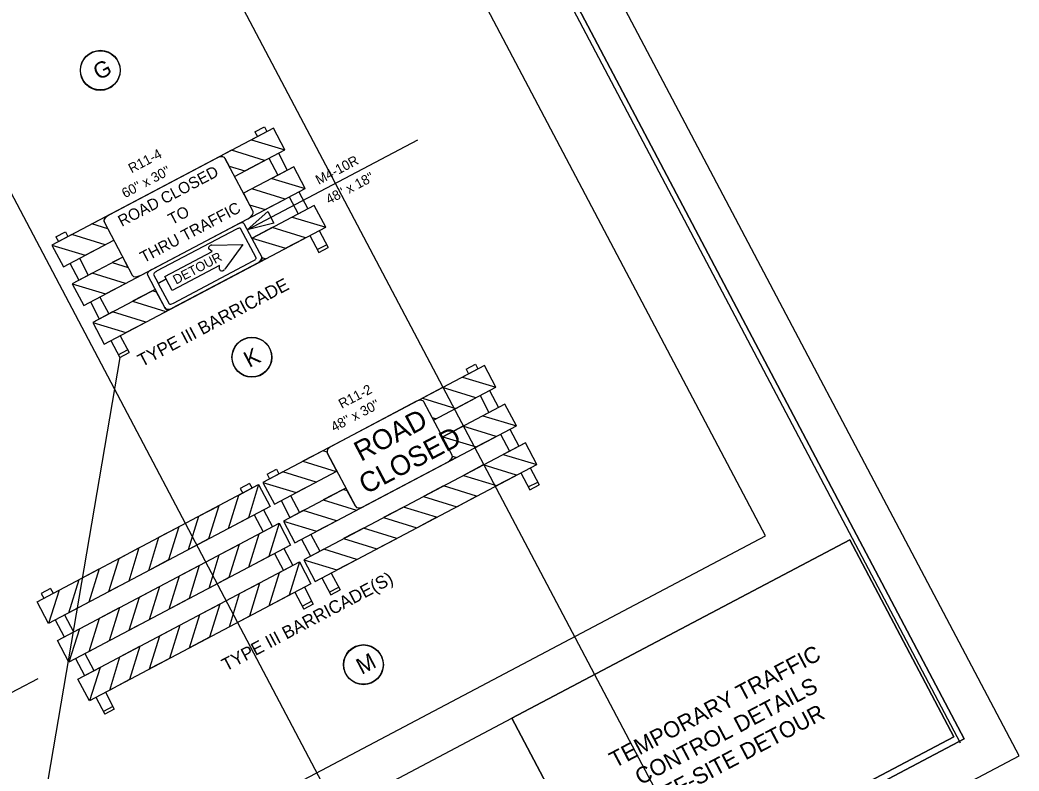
# Model space of a CAD drawing. Extents: x 1487176 to 2935813, y 497724 to 1002340.
# Drawn here: x 1489024 to 1489641, y 498716 to 499179 of the extents above; entities that cross this region are included whole.
import ezdxf

# ---------------------------------------------------------------- set-up
doc = ezdxf.new("R2010")
doc.units = 0
for name, color, linetype in [('DEV BORDER CELL', 7, 'Continuous'), ('DEV TYPE 3 BARRICADE DOUBLE WITH R11-2 CELL', 7, 'Continuous'), ('DEV TYPE 3 BARRICADE WITH R11-4 M4-10L CELL', 7, 'Continuous'), ('Gray Area Fill Shapes', 7, 'Continuous'), ('Scratch_Level_0', 7, 'Continuous'), ('Scratch_Level_1', 7, 'Continuous'), ('Scratch_Level_3', 7, 'Continuous'), ('Scratch_Level_5', 7, 'Continuous'), ('Sheet Plot Border Outside CELL', 7, 'Continuous'), ('WZ OSDHWYEND CELL', 7, 'Continuous'), ('WZ OSDHWYS CELL', 7, 'Continuous'), ('WZ OSDR CELL', 7, 'Continuous')]:
    doc.layers.add(name, color=color, linetype=linetype)

msp = doc.modelspace()

# ---------------------------------------------------------------- linework, layer by layer
at = {"layer": 'DEV BORDER CELL'}
for points in [[(1489116.94, 499663.96), (1487790.49, 498963.57), (1488280.77, 498035.05), (1489607.21, 498735.45)], [(1489536.46, 498858.41), (1489327.77, 498748.22), (1489391.98, 498626.62), (1489600.67, 498736.82)], [(1489226.96, 498694.98), (1489327.77, 498748.22), (1489391.98, 498626.62), (1489291.16, 498573.39)]]:
    msp.add_lwpolyline(points, close=True, dxfattribs=at)
at = {"layer": 'DEV TYPE 3 BARRICADE DOUBLE WITH R11-2 CELL'}
for p, q in [((1489310.86, 498966.09), (1489174.03, 498893.84)), ((1489310.86, 498966.09), (1489297.21, 498958.89)), ((1489299.46, 498963.78), (1489305.26, 498966.85)), ((1489305.26, 498966.85), (1489306.8, 498963.95)), ((1489317.95, 498952.68), (1489310.86, 498966.09)), ((1489317.95, 498952.68), (1489310.86, 498966.09)), ((1489299.46, 498963.78), (1489300.99, 498960.88)), ((1489297.21, 498958.89), (1489317.95, 498952.68)), ((1489284.9, 498952.38), (1489272.59, 498945.88)), ((1489279.36, 498932.3), (1489317.95, 498952.68)), ((1489305.4, 498946.05), (1489284.9, 498952.38)), ((1489308.07, 498947.46), (1489313.59, 498937.01)), ((1489313.88, 498950.53), (1489319.4, 498940.07)), ((1489272.59, 498945.88), (1489293.09, 498939.55)), ((1489323.47, 498942.22), (1489284.88, 498921.85)), ((1489293.09, 498939.55), (1489305.4, 498946.05)), ((1489323.47, 498942.22), (1489309.82, 498935.01)), ((1489330.55, 498928.8), (1489323.47, 498942.22)), ((1489330.55, 498928.8), (1489323.47, 498942.22)), ((1489309.82, 498935.01), (1489330.55, 498928.8)), ((1489193.71, 498856.55), (1489330.55, 498928.8)), ((1489280.78, 498933.05), (1489278.61, 498933.72)), ((1489278.61, 498933.72), (1489279.36, 498932.3)), ((1489279.36, 498932.3), (1489280.78, 498933.05)), ((1489297.51, 498928.51), (1489285.19, 498922.01)), ((1489318.01, 498922.18), (1489297.51, 498928.51)), ((1489320.68, 498923.59), (1489326.2, 498913.14)), ((1489326.49, 498926.66), (1489332.01, 498916.2)), ((1489336.07, 498918.35), (1489199.23, 498846.1)), ((1489285.19, 498922.01), (1489305.69, 498915.68)), ((1489305.69, 498915.68), (1489318.01, 498922.18)), ((1489336.07, 498918.35), (1489322.42, 498911.14)), ((1489343.16, 498904.93), (1489336.07, 498918.35)), ((1489343.16, 498904.93), (1489336.07, 498918.35)), ((1489210.96, 498913.34), (1489198.65, 498906.84)), ((1489213.6, 498912.53), (1489210.96, 498913.34)), ((1489219.7, 498900.8), (1489213.76, 498912.04)), ((1489322.42, 498911.14), (1489343.16, 498904.93)), ((1489198.65, 498906.84), (1489219.15, 498900.51)), ((1489206.32, 498832.68), (1489343.16, 498904.93)), ((1489235.78, 498878.77), (1489288.48, 498906.59)), ((1489288.48, 498906.59), (1489293.38, 498909.18)), ((1489293.38, 498909.18), (1489291, 498909.91)), ((1489310.11, 498904.64), (1489297.8, 498898.14)), ((1489330.61, 498898.31), (1489310.11, 498904.64)), ((1489186.34, 498900.34), (1489174.03, 498893.84)), ((1489176.56, 498898.89), (1489182.37, 498901.96)), ((1489176.56, 498898.89), (1489178.09, 498895.99)), ((1489181.11, 498880.42), (1489219.7, 498900.8)), ((1489182.37, 498901.96), (1489183.9, 498899.05)), ((1489206.84, 498894.01), (1489186.34, 498900.34)), ((1489219.15, 498900.51), (1489219.7, 498900.8)), ((1489297.8, 498898.14), (1489318.3, 498891.81)), ((1489318.3, 498891.81), (1489330.61, 498898.31)), ((1489333.28, 498899.72), (1489338.8, 498889.27)), ((1489339.09, 498902.79), (1489344.61, 498892.33)), ((1489034.52, 498820.17), (1489171.35, 498892.43)), ((1489159.04, 498885.93), (1489171.35, 498892.43)), ((1489165.75, 498893.19), (1489159.95, 498890.12)), ((1489171.35, 498892.43), (1489165.02, 498871.93)), ((1489165.75, 498893.19), (1489167.29, 498890.28)), ((1489171.35, 498892.43), (1489178.44, 498879.01)), ((1489174.03, 498893.84), (1489181.11, 498880.42)), ((1489174.03, 498893.84), (1489194.53, 498887.51)), ((1489194.53, 498887.51), (1489206.84, 498894.01)), ((1489285.48, 498891.64), (1489273.17, 498885.14)), ((1489305.98, 498885.31), (1489285.48, 498891.64)), ((1489337.88, 498891.01), (1489343.69, 498894.07)), ((1489338.8, 498889.27), (1489344.61, 498892.33)), ((1489152.71, 498865.43), (1489159.04, 498885.93)), ((1489159.95, 498890.12), (1489161.48, 498887.21)), ((1489225.22, 498890.34), (1489186.63, 498869.97)), ((1489190.98, 498885.64), (1489196.5, 498875.18)), ((1489223.57, 498889.47), (1489211.26, 498882.97)), ((1489226.09, 498888.69), (1489223.57, 498889.47)), ((1489231.15, 498879.1), (1489226.09, 498888.69)), ((1489293.67, 498878.8), (1489305.98, 498885.31)), ((1489134.41, 498872.92), (1489146.73, 498879.42)), ((1489146.73, 498879.42), (1489140.39, 498858.92)), ((1489185.18, 498882.57), (1489190.7, 498872.11)), ((1489211.26, 498882.97), (1489231.76, 498876.64)), ((1489273.17, 498885.14), (1489293.67, 498878.8)), ((1489178.44, 498879.01), (1489041.6, 498806.76)), ((1489128.08, 498852.42), (1489134.41, 498872.92)), ((1489168.56, 498873.8), (1489174.08, 498863.34)), ((1489174.37, 498876.86), (1489179.89, 498866.41)), ((1489198.94, 498876.47), (1489186.63, 498869.97)), ((1489219.44, 498870.14), (1489198.94, 498876.47)), ((1489231.76, 498876.64), (1489235.76, 498878.75)), ((1489260.8, 498878.6), (1489248.49, 498872.1)), ((1489281.3, 498872.27), (1489260.8, 498878.6)), ((1489047.12, 498796.3), (1489183.96, 498868.56)), ((1489165.02, 498871.93), (1489152.71, 498865.43)), ((1489171.64, 498862.06), (1489183.96, 498868.56)), ((1489183.96, 498868.56), (1489177.63, 498848.06)), ((1489183.96, 498868.56), (1489191.04, 498855.14)), ((1489186.63, 498869.97), (1489193.71, 498856.55)), ((1489186.63, 498869.97), (1489207.13, 498863.64)), ((1489207.13, 498863.64), (1489219.44, 498870.14)), ((1489248.49, 498872.1), (1489268.99, 498865.77)), ((1489268.99, 498865.77), (1489281.3, 498872.27)), ((1489109.79, 498859.92), (1489122.1, 498866.42)), ((1489122.1, 498866.42), (1489115.77, 498845.92)), ((1489165.31, 498841.55), (1489171.64, 498862.06)), ((1489203.59, 498861.76), (1489209.11, 498851.31)), ((1489236.17, 498865.6), (1489223.86, 498859.1)), ((1489256.67, 498859.27), (1489236.17, 498865.6)), ((1489191.04, 498855.14), (1489054.2, 498782.89)), ((1489103.46, 498839.42), (1489109.79, 498859.92)), ((1489140.39, 498858.92), (1489128.08, 498852.42)), ((1489147.02, 498849.05), (1489159.33, 498855.55)), ((1489159.33, 498855.55), (1489153, 498835.05)), ((1489197.78, 498858.7), (1489203.3, 498848.24)), ((1489223.86, 498859.1), (1489244.36, 498852.77)), ((1489244.36, 498852.77), (1489256.67, 498859.27)), ((1489085.1, 498846.89), (1489097.42, 498853.39)), ((1489097.42, 498853.39), (1489091.08, 498832.89)), ((1489140.69, 498828.55), (1489147.02, 498849.05)), ((1489181.17, 498849.93), (1489186.69, 498839.47)), ((1489186.98, 498852.99), (1489192.5, 498842.54)), ((1489211.55, 498852.6), (1489199.23, 498846.1)), ((1489232.05, 498846.27), (1489211.55, 498852.6)), ((1489059.72, 498772.43), (1489196.56, 498844.69)), ((1489078.77, 498826.39), (1489085.1, 498846.89)), ((1489115.77, 498845.92), (1489103.46, 498839.42)), ((1489122.39, 498836.05), (1489134.71, 498842.55)), ((1489134.71, 498842.55), (1489128.37, 498822.05)), ((1489177.63, 498848.06), (1489165.31, 498841.55)), ((1489184.25, 498838.18), (1489196.56, 498844.69)), ((1489196.56, 498844.69), (1489190.23, 498824.18)), ((1489196.56, 498844.69), (1489203.65, 498831.27)), ((1489199.23, 498846.1), (1489219.74, 498839.76)), ((1489199.23, 498846.1), (1489206.32, 498832.68)), ((1489219.74, 498839.76), (1489232.05, 498846.27)), ((1489060.48, 498833.88), (1489072.79, 498840.38)), ((1489072.79, 498840.38), (1489066.46, 498819.88)), ((1489116.06, 498815.55), (1489122.39, 498836.05)), ((1489177.92, 498817.68), (1489184.25, 498838.18)), ((1489216.19, 498837.89), (1489221.71, 498827.44)), ((1489054.15, 498813.38), (1489060.48, 498833.88)), ((1489203.65, 498831.27), (1489066.81, 498759.02)), ((1489091.08, 498832.89), (1489078.77, 498826.39)), ((1489153, 498835.05), (1489140.69, 498828.55)), ((1489159.62, 498825.18), (1489171.94, 498831.68)), ((1489171.94, 498831.68), (1489165.6, 498811.18)), ((1489210.38, 498834.83), (1489215.9, 498824.37)), ((1489034.52, 498820.17), (1489048.16, 498827.38)), ((1489042.86, 498828.29), (1489037.05, 498825.23)), ((1489037.05, 498825.23), (1489038.58, 498822.32)), ((1489048.16, 498827.38), (1489041.6, 498806.76)), ((1489042.86, 498828.29), (1489044.39, 498825.39)), ((1489097.71, 498823.02), (1489110.02, 498829.52)), ((1489110.02, 498829.52), (1489103.69, 498809.02)), ((1489153.29, 498804.68), (1489159.62, 498825.18)), ((1489190.23, 498824.18), (1489177.92, 498817.68)), ((1489193.77, 498826.06), (1489199.29, 498815.6)), ((1489199.58, 498829.12), (1489205.1, 498818.67)), ((1489214.98, 498826.11), (1489220.79, 498829.18)), ((1489215.9, 498824.37), (1489221.71, 498827.44)), ((1489041.6, 498806.76), (1489034.52, 498820.17)), ((1489041.6, 498806.76), (1489034.52, 498820.17)), ((1489066.46, 498819.88), (1489054.15, 498813.38)), ((1489091.38, 498802.51), (1489097.71, 498823.02)), ((1489128.37, 498822.05), (1489116.06, 498815.55)), ((1489135, 498812.18), (1489147.31, 498818.68)), ((1489147.31, 498818.68), (1489140.98, 498798.18)), ((1489204.18, 498820.41), (1489198.37, 498817.34)), ((1489205.1, 498818.67), (1489199.29, 498815.6)), ((1489051.47, 498811.97), (1489056.99, 498801.52)), ((1489073.08, 498810.01), (1489085.4, 498816.51)), ((1489085.4, 498816.51), (1489079.06, 498796.01)), ((1489128.66, 498791.68), (1489135, 498812.18)), ((1489045.67, 498808.9), (1489051.19, 498798.45)), ((1489066.75, 498789.51), (1489073.08, 498810.01)), ((1489103.69, 498809.02), (1489091.38, 498802.51)), ((1489110.31, 498799.14), (1489122.63, 498805.65)), ((1489122.63, 498805.65), (1489116.29, 498785.14)), ((1489165.6, 498811.18), (1489153.29, 498804.68)), ((1489047.12, 498796.3), (1489060.77, 498803.51)), ((1489060.77, 498803.51), (1489054.2, 498782.89)), ((1489103.98, 498778.64), (1489110.31, 498799.14)), ((1489054.2, 498782.89), (1489047.12, 498796.3)), ((1489054.2, 498782.89), (1489047.12, 498796.3)), ((1489079.06, 498796.01), (1489066.75, 498789.51)), ((1489140.98, 498798.18), (1489128.66, 498791.68)), ((1489064.08, 498788.1), (1489069.6, 498777.65)), ((1489085.69, 498786.14), (1489098, 498792.64)), ((1489098, 498792.64), (1489091.67, 498772.14)), ((1489058.27, 498785.03), (1489063.79, 498774.58)), ((1489079.35, 498765.64), (1489085.69, 498786.14)), ((1489116.29, 498785.14), (1489103.98, 498778.64)), ((1489059.72, 498772.43), (1489073.37, 498779.64)), ((1489073.37, 498779.64), (1489066.81, 498759.02)), ((1489066.81, 498759.02), (1489059.72, 498772.43)), ((1489066.81, 498759.02), (1489059.72, 498772.43)), ((1489091.67, 498772.14), (1489079.35, 498765.64)), ((1489076.68, 498764.23), (1489082.2, 498753.77)), ((1489070.87, 498761.16), (1489076.39, 498750.71)), ((1489081.28, 498755.52), (1489075.47, 498752.45)), ((1489082.2, 498753.77), (1489076.39, 498750.71))]:
    msp.add_line(p, q, dxfattribs=at)
for points in [[(1489268.79, 498943.88), (1489216.09, 498916.05)], [(1489290.82, 498910.6), (1489273.42, 498943.54)], [(1489213.76, 498912.04), (1489231.15, 498879.1)]]:
    msp.add_lwpolyline(points, dxfattribs=at)
for centre, major_axis, start_param, end_param in [((1489269.94, 498941.7), (3.48, 1.84), 0, 1.571024), ((1489217.24, 498913.88), (-3.48, -1.84), 4.712389, 6.283185), ((1489217.24, 498913.88), (-3.48, -1.84), 6.074789, 6.283185), ((1489287.34, 498908.77), (3.48, 1.84), 4.712162, 6.283185), ((1489287.33, 498908.77), (3.48, 1.84), 4.712497, 5.996053), ((1489234.63, 498880.94), (3.48, 1.84), 3.141593, 4.712389), ((1489234.63, 498880.94), (-3.48, -1.84), 0, 1.570796)]:
    msp.add_ellipse(centre, major_axis=major_axis, ratio=0.625, start_param=start_param, end_param=end_param, dxfattribs=at)
at = {"layer": 'DEV TYPE 3 BARRICADE WITH R11-4 M4-10L CELL'}
for p, q in [((1489180.49, 499112.61), (1489043.65, 499040.36)), ((1489180.49, 499112.61), (1489166.84, 499105.41)), ((1489169.08, 499110.3), (1489174.89, 499113.37)), ((1489169.08, 499110.3), (1489170.62, 499107.4)), ((1489174.89, 499113.37), (1489176.42, 499110.47)), ((1489187.57, 499099.2), (1489180.49, 499112.61)), ((1489187.57, 499099.2), (1489180.49, 499112.61)), ((1489164.34, 499049.73), (1489269.71, 499105.36)), ((1489166.84, 499105.41), (1489187.57, 499099.2)), ((1489154.53, 499098.9), (1489145.01, 499093.88)), ((1489175.03, 499092.57), (1489154.53, 499098.9)), ((1489156.44, 499082.76), (1489187.57, 499099.2)), ((1489183.51, 499097.05), (1489189.03, 499086.59)), ((1489150.51, 499094), (1489153.13, 499089.03)), ((1489153.13, 499089.03), (1489162.72, 499086.07)), ((1489162.72, 499086.07), (1489175.03, 499092.57)), ((1489177.7, 499093.98), (1489183.22, 499083.53)), ((1489193.09, 499088.74), (1489161.96, 499072.3)), ((1489193.09, 499088.74), (1489179.45, 499081.53)), ((1489200.18, 499075.32), (1489193.09, 499088.74)), ((1489200.18, 499075.32), (1489193.09, 499088.74)), ((1489179.45, 499081.53), (1489200.18, 499075.32)), ((1489063.34, 499003.07), (1489200.18, 499075.32)), ((1489167.13, 499075.03), (1489161.96, 499072.3)), ((1489187.63, 499068.7), (1489167.13, 499075.03)), ((1489196.11, 499073.18), (1489201.63, 499062.72)), ((1489205.7, 499064.87), (1489167.11, 499044.49)), ((1489175.32, 499062.2), (1489187.63, 499068.7)), ((1489190.3, 499070.11), (1489195.82, 499059.66)), ((1489205.7, 499064.87), (1489192.05, 499057.66)), ((1489212.78, 499051.45), (1489205.7, 499064.87)), ((1489212.78, 499051.45), (1489205.7, 499064.87)), ((1489068.28, 499053.36), (1489079.1, 499059.08)), ((1489078.22, 499050.29), (1489068.28, 499053.36)), ((1489075.93, 499054.62), (1489078.22, 499050.29)), ((1489075.93, 499054.62), (1489075.93, 499054.62)), ((1489192.05, 499057.66), (1489212.78, 499051.45)), ((1489055.96, 499046.86), (1489043.65, 499040.36)), ((1489046.18, 499045.41), (1489051.99, 499048.48)), ((1489051.99, 499048.48), (1489053.53, 499045.57)), ((1489076.47, 499040.53), (1489055.96, 499046.86)), ((1489075.95, 498979.2), (1489212.78, 499051.45)), ((1489157.6, 499050.1), (1489108.3, 499024.13)), ((1489169.75, 499032.44), (1489160.2, 499050.53)), ((1489179.74, 499051.16), (1489167.42, 499044.66)), ((1489200.24, 499044.83), (1489179.74, 499051.16)), ((1489202.91, 499046.24), (1489208.43, 499035.79)), ((1489208.72, 499049.31), (1489214.24, 499038.85)), ((1489043.65, 499040.36), (1489050.74, 499026.94)), ((1489043.65, 499040.36), (1489064.15, 499034.03)), ((1489046.18, 499045.41), (1489047.72, 499042.51)), ((1489050.74, 499026.94), (1489081.87, 499043.38)), ((1489064.15, 499034.03), (1489076.47, 499040.53)), ((1489142.48, 499040.37), (1489161.55, 499040.78)), ((1489161.55, 499040.78), (1489150.37, 499025.43)), ((1489167.42, 499044.66), (1489187.92, 499038.33)), ((1489187.92, 499038.33), (1489200.24, 499044.83)), ((1489207.51, 499037.53), (1489213.32, 499040.59)), ((1489113.44, 499020.88), (1489142.62, 499036.29)), ((1489142.62, 499036.29), (1489140.72, 499037.77)), ((1489208.43, 499035.79), (1489214.24, 499038.85)), ((1489054.8, 499029.09), (1489060.32, 499018.63)), ((1489087.39, 499032.93), (1489056.26, 499016.49)), ((1489060.61, 499032.16), (1489066.13, 499021.7)), ((1489087.39, 499032.93), (1489080.88, 499029.49)), ((1489080.88, 499029.49), (1489090.82, 499026.42)), ((1489090.82, 499026.42), (1489087.39, 499032.93)), ((1489147.1, 499027.78), (1489117.93, 499012.38)), ((1489170.71, 499029.24), (1489118.01, 499001.41)), ((1489118.72, 499004.53), (1489167.94, 499030.52)), ((1489147.23, 499025.44), (1489147.1, 499027.78)), ((1489170.71, 499029.24), (1489175.61, 499031.83)), ((1489175.61, 499031.83), (1489173.23, 499032.56)), ((1489068.57, 499022.99), (1489056.26, 499016.49)), ((1489089.07, 499016.66), (1489068.57, 499022.99)), ((1489106.44, 499022.14), (1489109.23, 499016.85)), ((1489056.26, 499016.49), (1489063.34, 499003.07)), ((1489056.26, 499016.49), (1489076.76, 499010.16)), ((1489076.76, 499010.16), (1489089.07, 499016.66)), ((1489109.23, 499016.85), (1489114.19, 499019.46)), ((1489114.27, 499019.3), (1489109.32, 499016.69)), ((1489109.32, 499016.69), (1489116.06, 499004.09)), ((1489114.19, 499019.46), (1489113.44, 499020.88)), ((1489117.93, 499012.38), (1489114.27, 499019.3)), ((1489107.45, 499012.99), (1489068.86, 498992.62)), ((1489105.8, 499012.12), (1489093.49, 499005.62)), ((1489108.32, 499011.34), (1489105.8, 499012.12)), ((1489113.39, 499001.75), (1489108.32, 499011.34)), ((1489067.41, 499005.22), (1489072.93, 498994.76)), ((1489073.21, 499008.28), (1489078.73, 498997.83)), ((1489093.49, 499005.62), (1489113.99, 498999.29)), ((1489081.17, 498999.12), (1489068.86, 498992.62)), ((1489101.67, 498992.79), (1489081.17, 498999.12)), ((1489113.99, 498999.29), (1489117.99, 499001.4)), ((1489068.86, 498992.62), (1489089.36, 498986.28)), ((1489068.86, 498992.62), (1489075.95, 498979.2)), ((1489089.36, 498986.28), (1489101.67, 498992.79)), ((1489085.82, 498984.41), (1489091.34, 498973.96)), ((1489080.01, 498981.35), (1489085.53, 498970.89)), ((1489084.61, 498972.63), (1489090.42, 498975.7)), ((1489085.53, 498970.89), (1489091.34, 498973.96)), ((1488929.73, 498717.15), (1489035.09, 498772.78))]:
    msp.add_line(p, q, dxfattribs=at)
for points in [[(1489145.01, 499093.88), (1489079.13, 499059.09)], [(1489167.9, 499061.06), (1489150.51, 499094)], [(1489161.96, 499072.3), (1489165.74, 499065.16), (1489175.32, 499062.2)], [(1489075.93, 499054.62), (1489093.32, 499021.68)], [(1489098.82, 499021.81), (1489164.7, 499056.59)], [(1489105.41, 499025.28), (1489158.11, 499053.11)], [(1489162.28, 499053.64), (1489173.5, 499032.38)], [(1489113.84, 499000.88), (1489102.62, 499022.14)]]:
    msp.add_lwpolyline(points, dxfattribs=at)
msp.add_lwpolyline([(1489180.78, 499053.77), (1489164.34, 499049.73), (1489176.95, 499061.03)], close=True, dxfattribs=at)
msp.add_lwpolyline([(1489180.78, 499053.77), (1489164.34, 499049.73), (1489176.95, 499061.03)], close=True, dxfattribs=at)
for centre, major_axis, ratio, start_param, end_param in [((1489146.16, 499091.7), (4.35, 2.3), 0.5, 0, 1.571024), ((1489146.16, 499091.7), (4.35, 2.3), 0.5, 0, 1.571024), ((1489080.28, 499056.92), (-4.35, -2.3), 0.5, 4.712389, 6.283185), ((1489080.28, 499056.92), (-4.35, -2.3), 0.5, 4.712304, 6.283185), ((1489163.55, 499058.76), (4.35, 2.3), 0.5, 4.712389, 6.283185), ((1489158.8, 499051.81), (3.48, 1.84), 0.375009, 0, 1.570796), ((1489157.97, 499049.35), (2.24, 1.18), 0.337508, 6.283178, 7.854173), ((1489142.07, 499038.87), (1.6, 0.84), 0.720018, 0.96961, 3.452569), ((1489167.54, 499031.28), (2.24, 1.18), 0.337508, 4.712203, 6.283178), ((1489169.57, 499031.42), (3.48, 1.84), 0.625, 4.712497, 5.996053), ((1489170.02, 499030.55), (-3.48, -1.84), 0.375009, 1.570796, 3.141593), ((1489097.67, 499023.98), (4.35, 2.3), 0.5, 3.141593, 4.712389), ((1489106.1, 499023.98), (-3.48, -1.84), 0.375009, 4.712162, 6.283185), ((1489108.74, 499023.35), (-2.24, -1.18), 0.337508, 4.712581, 6.283188), ((1489148.93, 499025.88), (1.6, 0.84), 0.720018, 2.830617, 5.313577), ((1489118.32, 499005.29), (-2.24, -1.18), 0.337508, 0.000003, 1.57061), ((1489116.87, 499003.59), (3.48, 1.84), 0.625, 3.141593, 4.712389), ((1489117.33, 499002.72), (-3.48, -1.84), 0.375009, 0, 1.570796)]:
    msp.add_ellipse(centre, major_axis=major_axis, ratio=ratio, start_param=start_param, end_param=end_param, dxfattribs=at)
at = {"layer": 'Gray Area Fill Shapes'}
for centre in [(1489073.53, 499148.05), (1489167.22, 498970.98), (1489236.14, 498781.2)]:
    msp.add_circle(centre, 12.25, dxfattribs=at)
at = {"layer": 'Scratch_Level_0'}
msp.add_lwpolyline([(1489096.07, 499596.4), (1487858.05, 498942.7), (1488301.64, 498102.61), (1489078.8, 498512.98), (1489023.58, 498617.56), (1489484.43, 498860.9)], close=True, dxfattribs=at)
at = {"layer": 'Scratch_Level_1'}
for p, q in [((1489064.57, 499755.99), (1489604.68, 498733.1)), ((1488905.4, 499671.94), (1489445.51, 498649.05)), ((1488746.22, 499587.89), (1489286.34, 498565)), ((1489085.53, 498970.89), (1488904.96, 497908.56))]:
    msp.add_line(p, q, dxfattribs=at)
at = {"layer": 'Scratch_Level_3'}
msp.add_lwpolyline([(1487790.49, 498963.57), (1488958.91, 499581.53), (1489116.94, 499663.96), (1489607.21, 498735.45), (1488280.77, 498035.05)], close=True, dxfattribs=at)
at = {"layer": 'Scratch_Level_5'}
msp.add_lwpolyline([(1489327.77, 498748.22), (1489536.46, 498858.41), (1489600.67, 498736.82), (1489391.98, 498626.62)], close=True, dxfattribs=at)
at = {"layer": 'Sheet Plot Border Outside CELL'}
msp.add_lwpolyline([(1488148.3, 497936.84), (1489640.99, 498725.01), (1489127.37, 499697.74), (1487634.68, 498909.56)], close=True, dxfattribs=at)
at = {"layer": 'WZ OSDHWYEND CELL'}
msp.add_circle((1489073.57, 499148.34), 12.25, dxfattribs=at)
at = {"layer": 'WZ OSDHWYS CELL'}
for centre in [(1489167.11, 498971.2), (1489236.02, 498781.42)]:
    msp.add_circle(centre, 12.25, dxfattribs=at)

# ---------------------------------------------------------------- texts
at = {"layer": 'DEV BORDER CELL'}
for s, p in [('TEMPORARY TRAFFIC', (1489391.4, 498717.26)), ('CONTROL DETAILS', (1489407.21, 498706.76)), ('OFF-SITE DETOUR', (1489414.88, 498691.96))]:
    msp.add_text(s, height=10, rotation=27.83509, dxfattribs=at).set_placement(p)
at = {"layer": 'DEV TYPE 3 BARRICADE DOUBLE WITH R11-2 CELL'}
for s, height, p in [('R11-2', 6, (1489222.68, 498939.15)), ("48'' x 30''", 6, (1489217.99, 498924.91)), ('ROAD', 12.369, (1489234.51, 498906.48)), ('CLOSED', 12.369, (1489237.51, 498886.23)), ('TYPE III BARRICADE(S)', 7.8816, (1489151.17, 498777.03))]:
    msp.add_text(s, height=height, rotation=27.83509, dxfattribs=at).set_placement(p)
at = {"layer": 'DEV TYPE 3 BARRICADE WITH R11-4 M4-10L CELL'}
for s, height, p in [('R11-4', 6, (1489092.85, 499084.52)), ('M4-10R', 6, (1489208.48, 499077.4)), ("60'' x 30''", 6, (1489088.8, 499069.2)), ('ROAD CLOSED', 7.0305, (1489086.8, 499051.5)), ('48" x 18"', 6, (1489214.82, 499065.39)), ('THRU TRAFFIC', 7.0305, (1489100.45, 499029.16)), ('TO', 7.031, (1489117.77, 499052.63)), ('DETOUR', 5.799, (1489120.34, 499015.91)), ('TYPE III BARRICADE', 7.8816, (1489099.23, 498964.96))]:
    msp.add_text(s, height=height, rotation=27.83509, dxfattribs=at).set_placement(p)
at = {"layer": 'WZ OSDR CELL'}
for s, p in [('G', (1489072.49, 499141.85)), ('K', (1489165.53, 498964.43)), ('M', (1489235.01, 498774.95))]:
    msp.add_text(s, height=10, rotation=27.83509, dxfattribs=at).set_placement(p)

doc.saveas('drawing.dxf')
